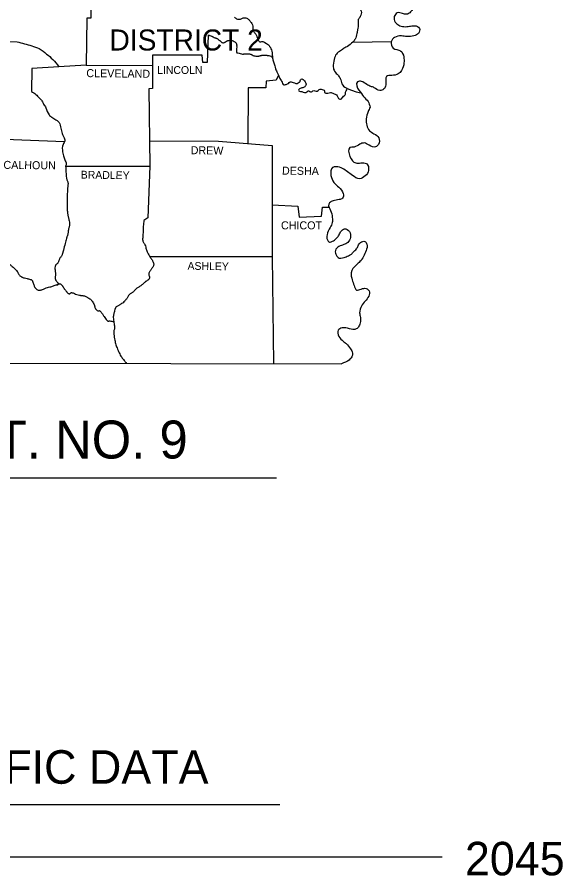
# Model space of a CAD drawing. Extents: x 670147 to 673275, y 705573 to 707613.
# Drawn here: x 672860.8 to 673153.6, y 706611.4 to 707072.7 of the extents above; entities that cross this region are included whole.
import ezdxf

# ---------------------------------------------------------------- set-up
doc = ezdxf.new("R2010")
doc.units = 0
doc.layers.add('2', color=7, linetype='Continuous')
doc.layers.add('Default', color=7, linetype='Continuous')

msp = doc.modelspace()

# ---------------------------------------------------------------- linework, layer by layer
at = {"layer": '2'}
msp.add_line((673040.87, 707059.35), (673061.62, 707059.66), dxfattribs=at)
for points in [[(672900.97, 707112.84), (672900.37, 707072.24), (672898.07, 707072.14), (672897.77, 707047.04)], [(672738.07, 707070.84), (672737.87, 707076.34), (672739.47, 707076.44), (672740.47, 707089.34), (672755.87, 707088.34), (672755.47, 707080.44), (672775.37, 707079.34), (672775.47, 707074.54), (672793.47, 707073.44), (672796.57, 707068.04), (672794.67, 707065.64), (672795.57, 707061.94), (672860.77, 707059.54)], [(672963.27, 707063.14), (672962.67, 707048.44), (672960.37, 707048.44), (672959.97, 707052.34), (672933.37, 707052.34), (672933.4, 707046.84)], [(672883.21, 707046.14), (672868.57, 707045.24), (672868.47, 707032.74)], [(672897.77, 707047.04), (672883.15, 707046.14)], [(672897.77, 707047.04), (672933.4, 707046.84)], [(672933.4, 707046.84), (672933.47, 707034.34), (672931.37, 707034.24), (672931.97, 706992.74)], [(673000.97, 707041.54), (672999.77, 707038.84), (672994.47, 707038.34), (672994.17, 707034.74), (672984.67, 707034.74), (672984.57, 707004.84)], [(673037.97, 707034.44), (673040.21, 707033.56), (673042.78, 707032.67), (673045.22, 707032.04)], [(672812.67, 707008.64), (672854.07, 707007.14), (672886.19, 707005.88)], [(672931.67, 707006.34), (672968.77, 707006.04), (672997.57, 707003.84)], [(672997.57, 707003.84), (672997.57, 706944.04), (672998.37, 706886.6)], [(672886.77, 706992.64), (672931.97, 706992.74)], [(672931.97, 706992.74), (672930.97, 706964.94), (672928.77, 706963.54)], [(672997.57, 706971.97), (673011.47, 706971.14), (673012.07, 706965.34), (673024.17, 706965.74), (673024.67, 706970.64), (673028.41, 706970.64)], [(672668.17, 706968.04), (672668.37, 706887.14), (673034.87, 706886.54)], [(672931.92, 706944.14), (672997.57, 706944.14)]]:
    msp.add_lwpolyline(points, dxfattribs=at)
for points in [[(673119.07, 707156.64), (673116.77, 707153.74), (673113.37, 707155.54), (673113.37, 707157.94), (673113.87, 707160.44), (673112.67, 707162.04), (673110.57, 707161.34), (673110.57, 707158.24), (673110.37, 707155.24), (673109.77, 707150.94), (673111.17, 707149.64), (673114.37, 707149.24), (673116.67, 707148.64), (673118.07, 707146.34), (673117.97, 707143.54), (673116.87, 707140.84), (673115.27, 707138.64), (673112.77, 707137.84), (673110.77, 707139.14), (673109.97, 707141.74), (673109.07, 707144.04), (673107.37, 707145.74), (673105.57, 707143.84), (673105.17, 707140.34), (673105.27, 707137.34), (673105.27, 707133.24), (673107.87, 707130.54), (673109.47, 707127.44), (673108.97, 707124.64), (673107.07, 707121.34), (673106.27, 707118.44), (673105.47, 707114.54), (673105.57, 707110.24), (673104.87, 707106.04), (673103.47, 707103.24), (673100.87, 707100.94), (673099.17, 707099.44), (673097.77, 707097.94), (673097.07, 707094.94), (673096.57, 707092.84), (673094.67, 707090.34), (673093.17, 707090.14), (673091.97, 707091.14), (673091.57, 707092.84), (673091.57, 707094.54), (673090.77, 707096.24), (673088.27, 707096.94), (673086.27, 707096.84), (673085.37, 707095.44), (673086.67, 707091.54), (673087.17, 707089.04), (673086.47, 707085.64), (673086.87, 707085.24), (673083.27, 707083.34), (673080.37, 707083.04), (673077.97, 707082.34), (673075.67, 707080.84), (673074.57, 707078.64), (673072.97, 707076.84), (673071.57, 707075.14), (673069.67, 707074.34), (673067.57, 707074.74), (673064.77, 707075.04), (673063.17, 707073.04), (673063.67, 707070.14), (673065.57, 707068.44), (673068.37, 707067.64), (673071.27, 707067.84), (673074.07, 707068.14), (673076.67, 707066.74), (673076.17, 707064.04), (673073.67, 707062.74), (673069.97, 707062.34), (673066.97, 707062.64), (673063.37, 707061.84), (673061.57, 707059.54), (673062.57, 707056.04), (673066.47, 707054.64), (673068.27, 707051.34), (673068.37, 707048.24), (673067.07, 707044.14), (673065.27, 707042.24), (673061.77, 707041.44), (673059.07, 707040.94), (673058.67, 707036.34), (673057.47, 707034.04), (673055.37, 707033.34), (673052.37, 707034.84), (673050.57, 707035.54), (673048.37, 707036.54), (673045.57, 707038.24), (673043.47, 707037.94), (673044.07, 707033.54), (673044.27, 707033.34), (673046.67, 707030.04), (673049.07, 707027.44), (673050.17, 707024.34)], [(673015.47, 707124.44), (673015.77, 707120.34), (673018.17, 707119.74), (673019.17, 707118.64), (673019.67, 707116.34), (673021.37, 707115.34), (673023.67, 707113.94), (673025.07, 707112.94), (673026.07, 707111.34), (673026.67, 707108.74), (673028.27, 707107.04), (673030.47, 707106.24), (673032.07, 707104.34), (673033.07, 707101.64), (673034.67, 707100.44), (673036.27, 707098.34), (673037.07, 707097.44), (673038.47, 707095.04), (673039.87, 707093.84), (673040.87, 707093.14), (673042.47, 707092.64), (673044.47, 707091.34), (673045.77, 707089.34), (673045.77, 707087.84), (673045.27, 707085.54), (673044.87, 707083.14), (673044.67, 707080.44), (673044.47, 707078.04), (673045.37, 707076.04), (673044.87, 707073.04), (673043.87, 707071.44), (673043.77, 707069.24), (673043.47, 707065.94), (673043.07, 707064.04), (673042.17, 707060.94), (673040.87, 707059.34)], [(672977.47, 707072.74), (672978.97, 707071.74), (672981.07, 707071.84), (672982.47, 707072.44), (672983.57, 707072.34), (672985.07, 707071.44), (672986.07, 707070.24), (672986.77, 707069.34), (672987.27, 707067.94), (672987.27, 707066.64), (672987.77, 707064.84), (672988.37, 707064.14), (672989.17, 707062.84), (672989.67, 707061.64), (672989.97, 707060.84), (672991.07, 707059.54), (672992.07, 707059.64), (672992.97, 707059.54), (672994.17, 707058.84), (672995.97, 707057.44), (672996.27, 707057.04), (672997.47, 707054.44), (672997.67, 707052.84), (672997.87, 707050.74), (672998.27, 707048.74), (672999.07, 707046.54), (672999.47, 707045.04), (673000.37, 707042.94), (673000.97, 707041.54), (673001.77, 707039.74), (673002.97, 707037.74), (673003.47, 707036.54), (673005.17, 707036.64), (673006.37, 707037.14), (673007.27, 707037.94), (673008.37, 707037.84), (673009.57, 707037.44), (673011.17, 707037.14), (673012.17, 707037.74), (673012.67, 707038.14), (673012.77, 707039.04), (673013.67, 707039.54), (673014.67, 707038.84), (673015.77, 707037.24), (673015.77, 707036.24), (673015.37, 707035.64), (673014.07, 707034.84), (673012.27, 707034.24), (673011.77, 707033.54), (673013.47, 707032.74), (673016.17, 707032.54), (673016.87, 707033.14), (673018.67, 707032.64), (673019.37, 707033.14), (673021.77, 707033.04), (673022.87, 707033.84), (673025.07, 707033.74), (673025.77, 707033.24), (673025.77, 707032.34), (673027.57, 707031.94), (673028.87, 707032.24), (673030.57, 707031.74), (673032.07, 707030.94), (673032.87, 707029.84), (673033.87, 707028.64), (673034.77, 707028.94), (673035.47, 707029.84), (673036.97, 707031.44), (673036.97, 707032.44), (673037.37, 707033.14), (673037.97, 707034.44)], [(672963.27, 707063.14), (672963.74, 707063.04), (672964.19, 707062.9), (672965.07, 707062.54), (672965.4, 707062.37), (672965.73, 707062.19), (672966.05, 707062.01), (672966.37, 707061.84), (672966.79, 707061.68), (672967.23, 707061.56), (672967.66, 707061.42), (672968.07, 707061.24), (672968.64, 707060.85), (672969.17, 707060.44), (672969.55, 707060.12), (672969.92, 707059.77), (672970.28, 707059.44), (672970.47, 707059.28), (672970.67, 707059.14), (672971.09, 707059), (672971.55, 707059.03), (672972.03, 707059.16), (672972.47, 707059.34), (672972.8, 707059.53), (672973.11, 707059.76), (672973.42, 707059.98), (672973.77, 707060.14), (672975.07, 707060.34), (672976.07, 707060.24), (672977.17, 707059.64), (672977.83, 707059.27), (672978.12, 707059.04), (672978.26, 707058.9), (672978.32, 707058.82), (672978.37, 707058.74), (672978.57, 707058.1), (672978.58, 707057.77), (672978.57, 707057.44), (672978.57, 707055.94), (672978.57, 707053.84), (672978.65, 707053.69), (672978.83, 707053.62), (672979.27, 707053.54), (672980.51, 707053.15), (672981.77, 707052.94), (672982.2, 707052.95), (672982.62, 707052.98), (672983.05, 707053.01), (672983.47, 707053.04), (672984.27, 707053.05), (672985.07, 707053.04), (672985.73, 707052.94), (672986.05, 707052.85), (672986.37, 707052.74), (672986.66, 707052.6), (672986.92, 707052.43), (672987.19, 707052.26), (672987.47, 707052.14), (672988.27, 707051.94), (672989.47, 707051.74), (672990.47, 707051.84), (672990.9, 707051.94), (672991.32, 707052.07), (672991.74, 707052.19), (672992.17, 707052.24), (672993.17, 707052.24), (672994.77, 707052.24), (672995.27, 707052.21), (672995.52, 707052.18), (672995.77, 707052.14), (672996.84, 707051.74), (672997.35, 707051.43), (672997.83, 707051.1)], [(672860.77, 707059.54), (672868.57, 707057.34), (672872.57, 707055.84), (672876.57, 707052.94), (672879.87, 707050.04), (672883.15, 707046.14)], [(673040.87, 707059.34), (673038.07, 707057.04), (673036.27, 707056.04), (673034.37, 707054.64), (673032.07, 707052.94), (673030.97, 707050.04), (673030.37, 707046.04), (673031.17, 707043.64), (673032.97, 707041.54), (673034.17, 707039.84), (673035.07, 707036.84), (673037.27, 707034.74), (673037.97, 707034.44)], [(672868.47, 707032.74), (672870.77, 707031.24), (672872.67, 707029.24), (672874.07, 707027.74), (672874.97, 707026.04), (672876.17, 707024.04), (672877.87, 707020.24), (672879.37, 707018.94), (672881.47, 707017.64), (672882.77, 707016.74), (672884.07, 707013.84), (672884.67, 707010.94), (672885.77, 707008.34), (672886.27, 707006.34), (672885.37, 707004.34), (672885.17, 707000.34), (672885.77, 706997.64), (672886.57, 706995.64), (672887.07, 706993.34), (672886.77, 706992.64)], [(673050.17, 707024.34), (673049.17, 707022.04), (673048.07, 707018.04), (673048.37, 707014.64), (673049.87, 707011.74), (673052.27, 707010.14), (673054.87, 707007.84), (673054.67, 707004.34), (673053.17, 707003.04), (673049.67, 707003.94), (673046.97, 707005.14), (673044.67, 707004.44), (673041.57, 707002.94), (673039.27, 707002.64), (673039.37, 706997.84), (673042.47, 706994.44), (673045.17, 706994.44), (673048.27, 706994.04), (673049.37, 706990.44), (673047.57, 706987.44), (673044.57, 706985.94), (673040.77, 706987.74), (673038.07, 706989.64), (673035.37, 706991.44), (673031.97, 706992.34), (673030.07, 706991.94), (673029.17, 706987.74), (673030.77, 706983.94), (673033.37, 706981.34), (673035.77, 706977.94), (673035.37, 706975.44), (673033.57, 706974.74), (673030.37, 706974.04), (673028.47, 706973.04), (673027.97, 706972.24), (673028.97, 706968.84), (673029.87, 706965.14), (673029.87, 706962.34), (673028.77, 706959.74), (673027.07, 706955.74), (673027.27, 706953.14), (673028.47, 706951.94), (673029.97, 706952.34), (673031.97, 706953.74), (673033.27, 706955.34), (673034.37, 706957.34), (673036.47, 706959.04), (673039.07, 706957.54), (673039.67, 706954.44), (673038.17, 706951.74), (673036.07, 706950.54), (673033.47, 706949.54), (673031.57, 706947.34), (673032.07, 706944.74), (673033.57, 706943.34), (673037.27, 706944.04), (673039.77, 706945.14), (673041.17, 706946.54), (673042.87, 706948.24), (673043.77, 706949.94), (673045.07, 706951.74), (673047.37, 706952.24), (673048.47, 706950.74), (673048.07, 706947.34), (673046.67, 706944.14), (673044.77, 706941.44), (673042.67, 706939.54), (673040.07, 706935.44), (673040.57, 706931.64), (673041.57, 706928.54), (673042.97, 706926.14), (673045.37, 706926.64), (673048.07, 706926.94), (673049.67, 706925.64), (673049.47, 706922.84), (673047.47, 706920.14), (673045.57, 706917.54), (673044.57, 706913.94), (673044.97, 706911.44), (673044.97, 706909.14), (673044.17, 706906.64), (673042.77, 706905.24), (673039.07, 706905.34), (673035.17, 706905.74), (673033.07, 706904.54), (673033.47, 706901.14), (673035.77, 706898.64), (673037.37, 706897.34), (673039.67, 706894.54), (673040.67, 706892.24), (673040.37, 706890.24), (673038.97, 706888.54), (673034.87, 706886.54)], [(672886.77, 706992.64), (672886.85, 706991.09), (672886.94, 706989.54), (672887.17, 706986.44), (672887.35, 706985.68), (672887.66, 706984.94), (672887.95, 706984.2), (672888.04, 706983.82), (672888.07, 706983.44), (672888.03, 706982.64), (672887.93, 706981.84), (672887.83, 706981.04), (672887.77, 706980.24), (672887.67, 706977.14), (672887.67, 706974.34), (672887.67, 706971.64), (672887.67, 706968.84), (672887.87, 706966.84), (672888.02, 706966.11), (672888.21, 706965.39), (672888.4, 706964.67), (672888.57, 706963.94), (672888.82, 706962.59), (672888.88, 706961.91), (672888.87, 706961.24), (672888.77, 706960.59), (672888.6, 706959.94), (672888.42, 706959.29), (672888.27, 706958.64), (672888.2, 706958.04), (672888.15, 706957.44), (672888.08, 706956.83), (672887.97, 706956.24), (672887.79, 706955.63), (672887.58, 706955.04), (672887.36, 706954.44), (672887.17, 706953.84), (672886.47, 706951.14), (672885.67, 706947.64), (672885.36, 706946.48), (672885.18, 706945.91), (672884.97, 706945.34), (672884.67, 706944.72), (672884.3, 706944.12), (672883.92, 706943.54), (672883.57, 706942.94), (672883.33, 706942.4), (672883.12, 706941.84), (672882.91, 706941.28), (672882.67, 706940.74), (672882.36, 706940.37), (672881.95, 706940.07), (672881.54, 706939.75), (672881.38, 706939.56), (672881.27, 706939.34), (672881.05, 706938.14), (672881.07, 706936.94), (672881.14, 706936.39), (672881.23, 706935.84), (672881.32, 706935.29), (672881.37, 706934.74), (672881.35, 706934.24), (672881.28, 706933.74), (672881.2, 706933.24), (672881.17, 706932.74), (672881.35, 706931.77), (672881.87, 706930.84), (672882.21, 706930.43), (672882.57, 706930.05), (672883.3, 706929.55)], [(672928.77, 706963.54), (672928.47, 706960.44), (672928.37, 706957.54), (672928.17, 706954.74), (672928.12, 706953.69), (672928.12, 706953.16), (672928.17, 706952.64), (672928.37, 706952.03), (672928.72, 706951.47), (672929.09, 706950.92), (672929.37, 706950.34), (672930.07, 706948.14), (672930.77, 706946.24), (672932.17, 706943.74), (672932.48, 706943.26), (672932.82, 706942.79), (672933.16, 706942.33), (672933.47, 706941.84), (672933.98, 706940.5), (672934.03, 706939.8), (672933.87, 706939.14), (672933.07, 706937.74), (672932.71, 706937.21), (672932.32, 706936.69), (672931.93, 706936.17), (672931.57, 706935.64), (672931.41, 706934.73), (672931.62, 706933.68), (672931.79, 706932.67), (672931.47, 706931.84), (672931.27, 706931.66), (672931.05, 706931.5), (672930.58, 706931.22), (672930.11, 706930.95), (672929.67, 706930.64), (672928.54, 706929.62), (672927.97, 706929.11), (672927.37, 706928.64), (672926.07, 706927.74), (672924.67, 706926.84), (672924.26, 706926.48), (672923.9, 706926.07), (672923.55, 706925.64), (672923.17, 706925.24), (672922.64, 706924.85), (672922.06, 706924.51), (672921.48, 706924.17), (672920.97, 706923.74), (672920.53, 706923.15), (672920.16, 706922.51), (672919.79, 706921.85), (672919.37, 706921.24), (672918.96, 706920.73), (672918.53, 706920.23), (672917.57, 706919.34), (672916.07, 706918.34), (672915.55, 706918.02), (672915.02, 706917.72), (672914.23, 706917.23), (672913.97, 706917.04), (672913.61, 706916.63), (672913.37, 706916.14), (672913.07, 706915.04), (672912.81, 706914.12), (672912.57, 706913.2), (672912.41, 706912.27), (672912.37, 706911.34), (672912.49, 706909.99), (672912.67, 706908.64), (672913.07, 706906.24), (672913.03, 706905.49), (672912.82, 706904.74), (672912.62, 706903.99), (672912.57, 706903.24), (672913.07, 706899.94), (672913.57, 706897.34), (672914.37, 706895.04), (672915.47, 706892.44), (672916.13, 706891.22), (672916.87, 706890.04), (672918.13, 706888.34), (672919.51, 706886.73)], [(672829.07, 706940.44), (672830.67, 706941.54), (672832.17, 706942.14), (672832.92, 706942.01), (672833.3, 706941.92), (672833.67, 706941.84), (672835.27, 706941.64), (672835.62, 706941.66), (672835.97, 706941.73), (672836.32, 706941.8), (672836.67, 706941.84), (672838.47, 706941.54), (672838.87, 706941.34), (672839.24, 706941.1), (672839.6, 706940.86), (672839.97, 706940.64), (672840.8, 706940.19), (672841.67, 706939.94), (672843.37, 706939.94), (672844.87, 706939.94), (672845.23, 706939.81), (672845.53, 706939.53), (672845.83, 706939.22), (672846.17, 706939.04), (672846.76, 706938.96), (672847.38, 706938.94), (672847.99, 706938.99), (672848.57, 706939.14), (672849.07, 706939.33), (672849.57, 706939.55), (672850.07, 706939.75), (672850.57, 706939.94), (672852.57, 706940.54), (672853.25, 706940.74), (672853.94, 706940.92), (672854.62, 706940.98), (672854.96, 706940.94), (672855.27, 706940.84), (672856.52, 706940.07), (672857.67, 706939.14), (672858.53, 706938.45), (672859.37, 706937.74), (672860.77, 706936.14), (672861.05, 706935.71), (672861.27, 706935.25), (672861.5, 706934.78), (672861.77, 706934.34), (672862.87, 706933.34), (672863.31, 706933.12), (672863.76, 706932.93), (672864.67, 706932.64), (672866.07, 706932.34), (672867.77, 706931.84), (672868.26, 706931.71), (672868.48, 706931.6), (672868.67, 706931.44), (672868.96, 706930.99), (672869.14, 706930.51), (672869.29, 706930.02), (672869.47, 706929.54), (672869.61, 706929.21), (672869.73, 706928.88), (672869.96, 706928.23), (672870.27, 706927.58), (672870.49, 706927.26), (672870.62, 706927.1), (672870.77, 706926.94), (672871.38, 706926.44), (672872.01, 706926.11), (672872.64, 706925.98), (672873.27, 706926.04), (672874.05, 706926.31), (672874.82, 706926.64), (672875.59, 706926.97), (672876.37, 706927.24), (672878.87, 706927.94), (672880.67, 706928.54), (672881.77, 706928.94), (672882.02, 706928.99), (672882.27, 706929), (672882.53, 706929), (672882.77, 706929.04), (672882.79, 706929.06), (672882.76, 706929.08), (672882.63, 706929.13), (672882.49, 706929.19), (672882.46, 706929.22), (672882.47, 706929.24), (672882.76, 706929.38), (672883.07, 706929.49), (672883.67, 706929.54), (672883.96, 706929.43), (672884.26, 706929.25), (672884.77, 706928.74), (672884.96, 706928.47), (672885.13, 706928.19), (672885.29, 706927.91), (672885.47, 706927.64), (672886.67, 706926.04), (672887.2, 706925.34), (672887.47, 706924.99), (672887.77, 706924.64), (672888.02, 706924.44), (672888.3, 706924.29), (672888.59, 706924.2), (672888.87, 706924.14), (672889.15, 706924.23), (672889.42, 706924.47), (672889.69, 706924.69), (672889.97, 706924.74), (672891.47, 706924.24), (672892.77, 706923.74), (672894.27, 706923.34), (672894.6, 706923.3), (672894.92, 706923.28), (672895.25, 706923.27), (672895.57, 706923.24), (672897.27, 706922.84), (672898.57, 706922.14), (672899.77, 706921.44), (672900.97, 706920.14), (672902.17, 706918.14), (672902.3, 706917.76), (672902.38, 706917.35), (672902.45, 706916.94), (672902.57, 706916.54), (672903.17, 706915.65), (672903.55, 706915.28), (672903.97, 706914.94), (672904.29, 706914.88), (672904.66, 706914.97), (672905.01, 706915.05), (672905.27, 706914.94), (672905.76, 706914.3), (672906.24, 706913.65), (672907.17, 706912.34), (672907.87, 706911.34), (672908.52, 706910.38), (672908.9, 706909.93), (672909.12, 706909.73), (672909.37, 706909.54), (672909.64, 706909.46), (672909.92, 706909.48), (672910.2, 706909.54), (672910.47, 706909.54), (672912.61, 706909.13)]]:
    msp.add_spline(points, degree=3, dxfattribs=at)
at = {"layer": 'Default'}
for p, q in [((672674.6, 706825.15), (673000.04, 706825.15)), ((672681.81, 706649.78), (673001.81, 706649.78)), ((672740.39, 706621.66), (673088.94, 706621.66))]:
    msp.add_line(p, q, dxfattribs=at)

# ---------------------------------------------------------------- texts
at = {"layer": '2'}
for s, height, p in [('DISTRICT 2', 11.299, (672910.32, 707054.83)), ('LINCOLN', 4.2, (672935.87, 707042.24)), ('CHICOT', 4.3, (673002.37, 706958.74))]:
    msp.add_text(s, height=height, dxfattribs=at).set_placement(p)
for s, height, rotation, p in [('CLEVELAND', 4.301, 359.3377, (672897.87, 707040.54)), ('DREW', 4.299, 359.2258, (672953.87, 706999.14)), ('CALHOUN', 4.301, 359.3634, (672853.37, 706991.24)), ('BRADLEY', 4.199, 359.1449, (672894.87, 706986.04)), ('DESHA', 4.299, 359.3704, (673002.87, 706988.14)), ('ASHLEY', 4.2, 359.2361, (672952.17, 706937.04))]:
    msp.add_text(s, height=height, rotation=rotation, dxfattribs=at).set_placement(p)
at = {"layer": 'Default'}
for s, height, p in [('  ARK. HWY. DIST. NO. 9', 20.4, (672638.56, 706835.61)), ('DESIGN TRAFFIC DATA', 18, (672692.01, 706660.88)), ('2045', 18, (673101.09, 706611.66))]:
    msp.add_text(s, height=height, dxfattribs=at).set_placement(p)

doc.saveas('drawing.dxf')
